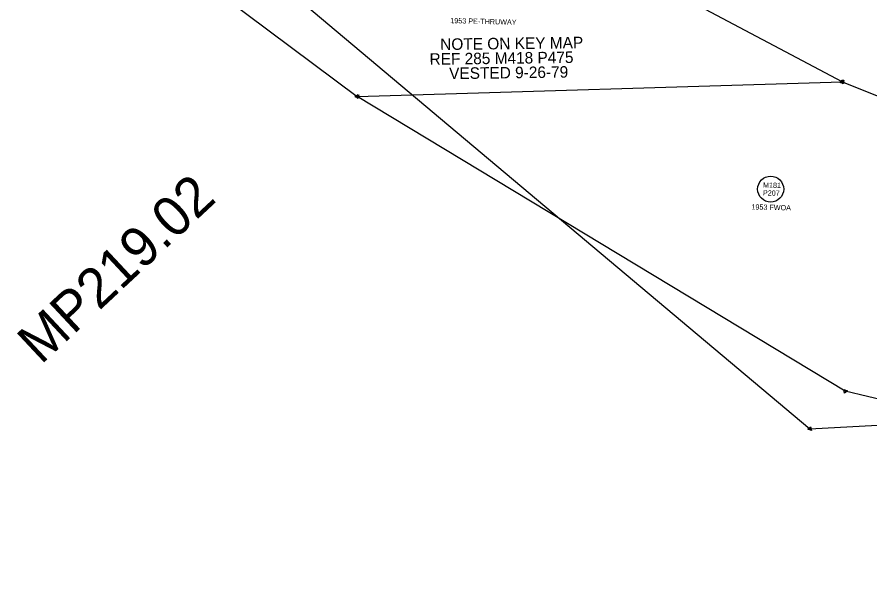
# Model space of a CAD drawing. Extents: x 325029 to 414988, y 1517527 to 1550420.
# Drawn here: x 363992 to 364852, y 1523169 to 1523742 of the extents above; entities that cross this region are included whole.
import ezdxf

# ---------------------------------------------------------------- set-up
doc = ezdxf.new("R2010")
doc.units = 0
for name, color, linetype in [('Level 56', 7, 'Continuous'), ('MEE', 7, 'Continuous'), ('MHBWOA', 7, 'Continuous'), ('MRBL2', 7, 'Continuous'), ('NNSH_P_T', 7, 'Continuous'), ('S_C', 7, 'Continuous')]:
    doc.layers.add(name, color=color, linetype=linetype)

msp = doc.modelspace()

# ---------------------------------------------------------------- linework, layer by layer
at = {"layer": 'Level 56'}
msp.add_circle((364752.17, 1523568.38), 13.12, dxfattribs=at)
at = {"layer": 'MEE'}
for p, q in [((364824.36, 1523676.63), (364563.22, 1523815.09)), ((364151.51, 1523799.25), (364335.19, 1523661.88))]:
    msp.add_line(p, q, dxfattribs=at)
for points in [[(364822.24, 1523677.12), (364825.85, 1523678.22)], [(364824.99, 1523674.54), (364822.24, 1523677.12)], [(364825.85, 1523678.22), (364824.99, 1523674.54)], [(364333.06, 1523661.4), (364335.85, 1523663.95)], [(364336.66, 1523660.26), (364333.06, 1523661.4)], [(364335.85, 1523663.95), (364336.66, 1523660.26)]]:
    msp.add_lwpolyline(points, dxfattribs=at)
for centre in [(364824.36, 1523676.63), (364335.19, 1523661.88)]:
    msp.add_circle(centre, 0.227, dxfattribs=at)
at = {"layer": 'MHBWOA'}
for p, q in [((364335.19, 1523661.88), (364824.36, 1523676.63)), ((364824.36, 1523676.63), (365023.22, 1523596.42)), ((364827.47, 1523364.5), (364335.19, 1523661.88)), ((365635.23, 1523168.88), (364827.47, 1523364.5))]:
    msp.add_line(p, q, dxfattribs=at)
for points in [[(364822.2, 1523676.32), (364825.17, 1523678.65)], [(364825.7, 1523674.9), (364822.2, 1523676.32)], [(364822.5, 1523675.48), (364824.29, 1523678.8)], [(364824.29, 1523678.8), (364826.28, 1523675.59)], [(364825.17, 1523678.65), (364825.7, 1523674.9)], [(364826.28, 1523675.59), (364822.5, 1523675.48)], [(364333.09, 1523662.43), (364336.73, 1523663.43)], [(364335.77, 1523659.77), (364333.09, 1523662.43)], [(364336.73, 1523663.43), (364335.77, 1523659.77)], [(364826.64, 1523362.49), (364826.14, 1523366.24)], [(364826.14, 1523366.24), (364829.64, 1523364.8)], [(364829.64, 1523364.8), (364826.64, 1523362.49)]]:
    msp.add_lwpolyline(points, dxfattribs=at)
for centre, radius in [((364824.36, 1523676.62), 1.09), ((364824.36, 1523676.63), 1.09), ((364335.19, 1523661.88), 0.227), ((364827.47, 1523364.5), 0.227)]:
    msp.add_circle(centre, radius, dxfattribs=at)
at = {"layer": 'MRBL2'}
for p, q in [((364282.48, 1523754.5), (364791.76, 1523326.52)), ((364791.76, 1523326.52), (366480.7, 1523417.94))]:
    msp.add_line(p, q, dxfattribs=at)
for points in [[(364789.63, 1523326.08), (364792.45, 1523328.58)], [(364793.21, 1523324.88), (364789.63, 1523326.08)], [(364792.45, 1523328.58), (364793.21, 1523324.88)]]:
    msp.add_lwpolyline(points, dxfattribs=at)
msp.add_circle((364791.76, 1523326.52), 0.227, dxfattribs=at)

# ---------------------------------------------------------------- texts
at = {"layer": 'Level 56'}
for s, height, p in [('1953 PE-THRUWAY', 5.2493, (364429, 1523735.87)), ('M181', 5.249, (364744.41, 1523569.9)), ('P207', 5.249, (364744.33, 1523562.02)), ('1953 FWOA', 5.249, (364732.71, 1523547.87))]:
    msp.add_text(s, height=height, rotation=358.49067, dxfattribs=at).set_placement(p)
at = {"layer": 'NNSH_P_T'}
for s, p in [('NOTE ON KEY MAP', (364418.93, 1523708.67)), ('REF 285 M418 P475', (364408.19, 1523693.79)), ('VESTED 9-26-79', (364427.96, 1523679.31))]:
    msp.add_text(s, height=11.6264, rotation=0.74623, dxfattribs=at).set_placement(p)
at = {"layer": 'S_C'}
msp.add_text('MP219.02', height=40.013, rotation=43.03146, dxfattribs=at).set_placement((364016.2, 1523390.49))

doc.saveas('drawing.dxf')
